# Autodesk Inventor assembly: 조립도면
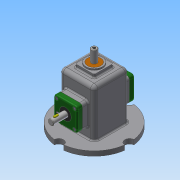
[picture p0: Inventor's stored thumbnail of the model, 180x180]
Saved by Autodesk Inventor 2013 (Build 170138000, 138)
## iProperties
Created: 2018-07
Part Number: 조립도면
Document SubType Name: Assembly
Designer: Administrator
Author: Administrator
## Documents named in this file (16)
- C:\Users\Administrator\Desktop\480708V1012\조립도면.iam
- C:\Users\Administrator\Desktop\480708V1012\본체1.ipt
- C:\Users\Administrator\Desktop\480708V1012\V벨트풀리.ipt
- C:\Users\Administrator\Desktop\480708V1012\고정핀 1.2x8.ipt
- C:\Users\Administrator\Desktop\480708V1012\뒤커버.ipt
- C:\Users\Administrator\Desktop\480708V1012\링크.ipt
- C:\Users\Administrator\Desktop\480708V1012\멈춤나사 M3x8.ipt
- C:\Users\Administrator\Desktop\480708V1012\베어링 12x32x10.ipt
- C:\Users\Administrator\Desktop\480708V1012\볼트 M4.ipt
- C:\Users\Administrator\Desktop\480708V1012\부시.ipt
- C:\Users\Administrator\Desktop\480708V1012\슬라이드.ipt
- C:\Users\Administrator\Desktop\480708V1012\앞커버.ipt
- C:\Users\Administrator\Desktop\480708V1012\오일 실 12 25 7.ipt
- C:\Users\Administrator\Desktop\480708V1012\키 4x4x10.ipt
- C:\Users\Administrator\Desktop\480708V1012\편심축.ipt
- C:\Users\Administrator\Desktop\480708V1012\핀 5x18.ipt
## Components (3 placed, 3 different names)
1. V벨트풀리:1
2. 고정핀 1.2x8:1
3. 핀 5x18:1
